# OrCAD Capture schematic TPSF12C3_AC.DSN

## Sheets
1 Test Bench: size C
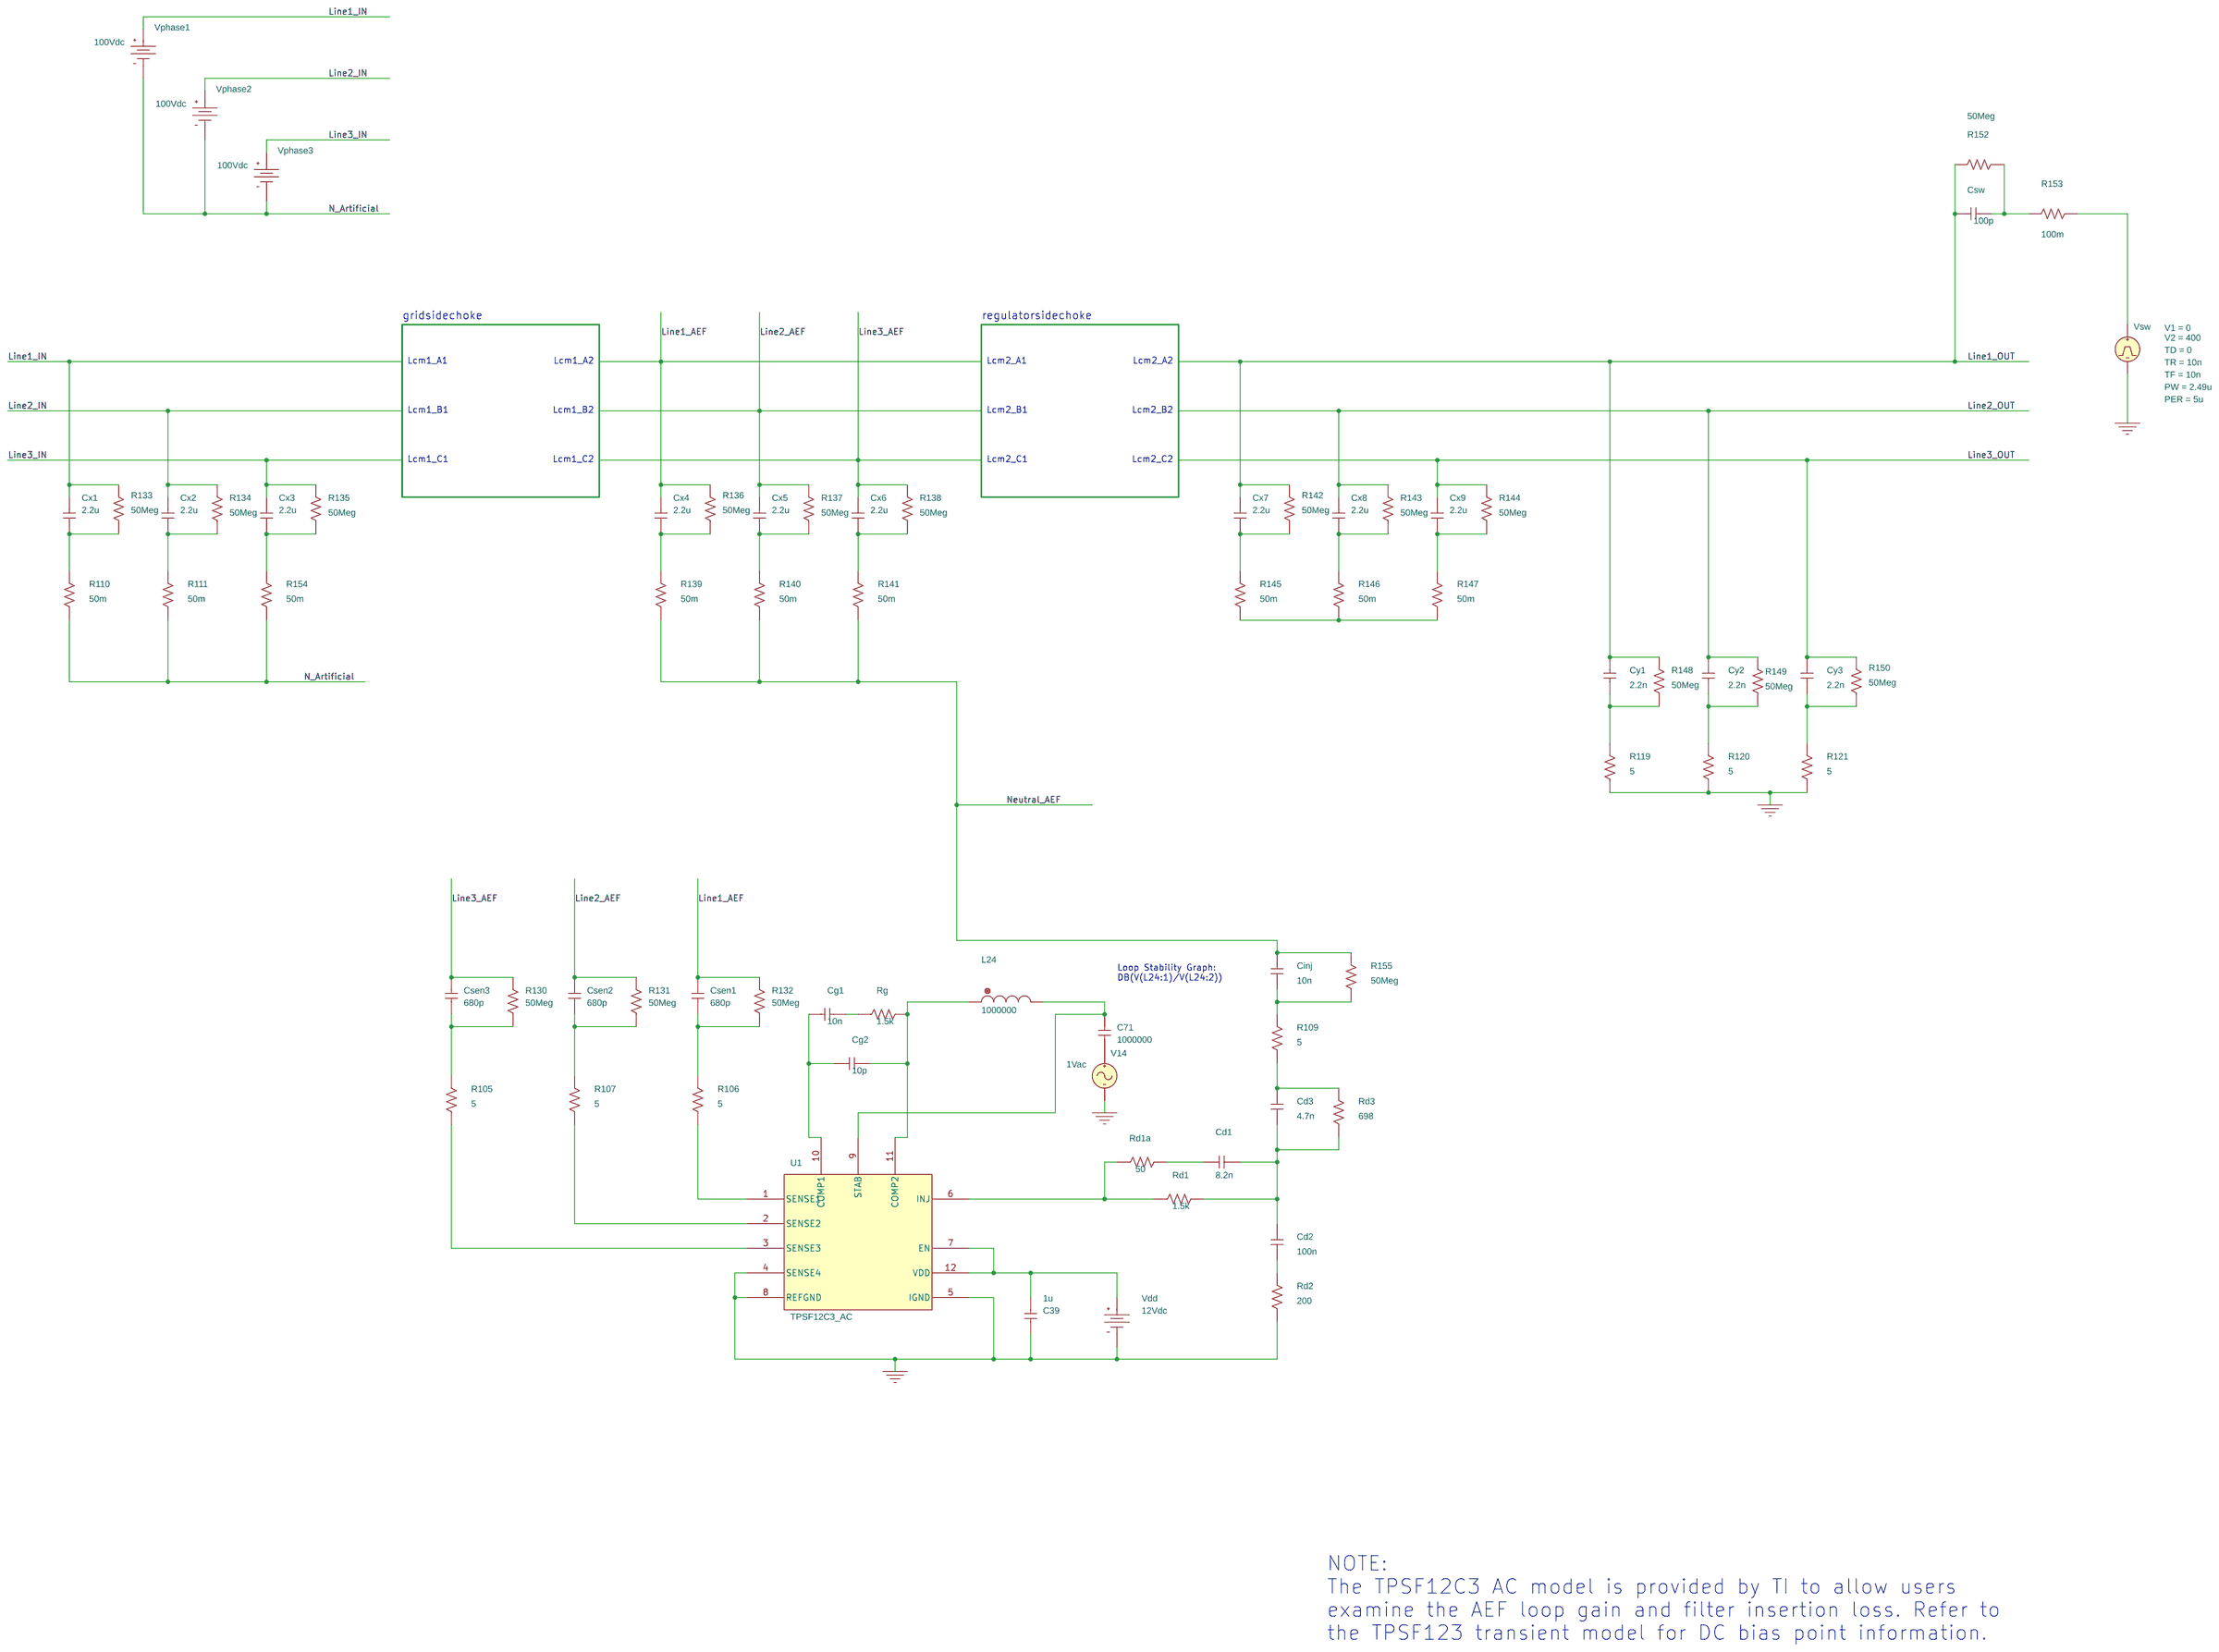
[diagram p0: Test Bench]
2 3 wire choke model: size C; block regulatorsidechoke
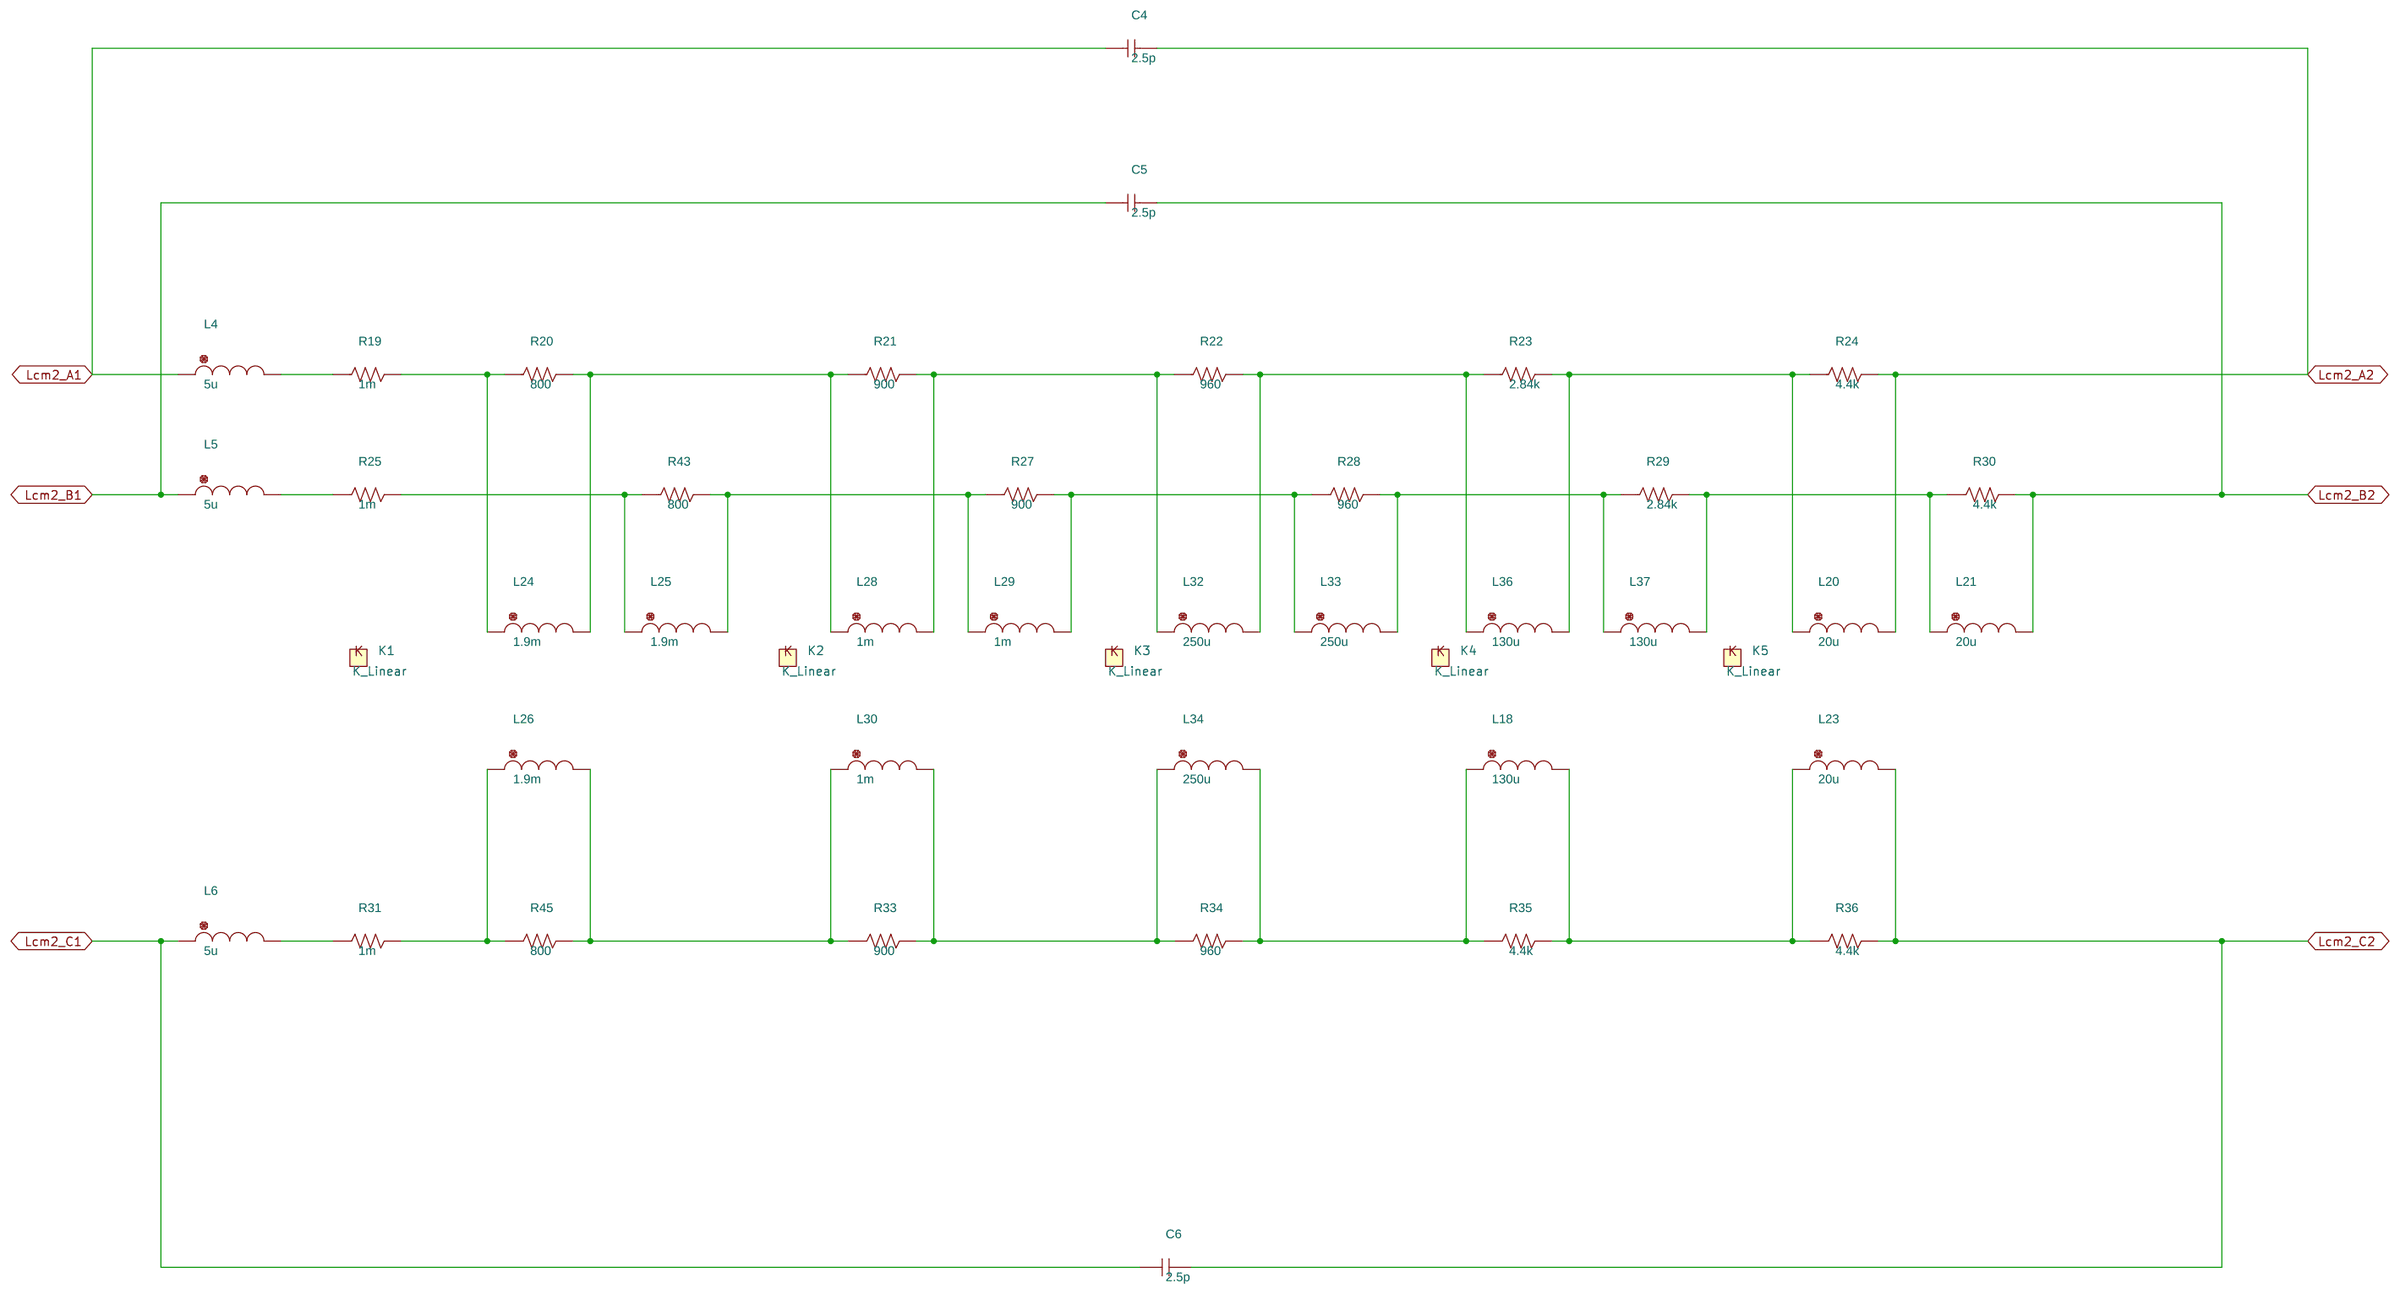
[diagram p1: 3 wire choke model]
3 3 wire choke model (2): size B; block gridsidechoke
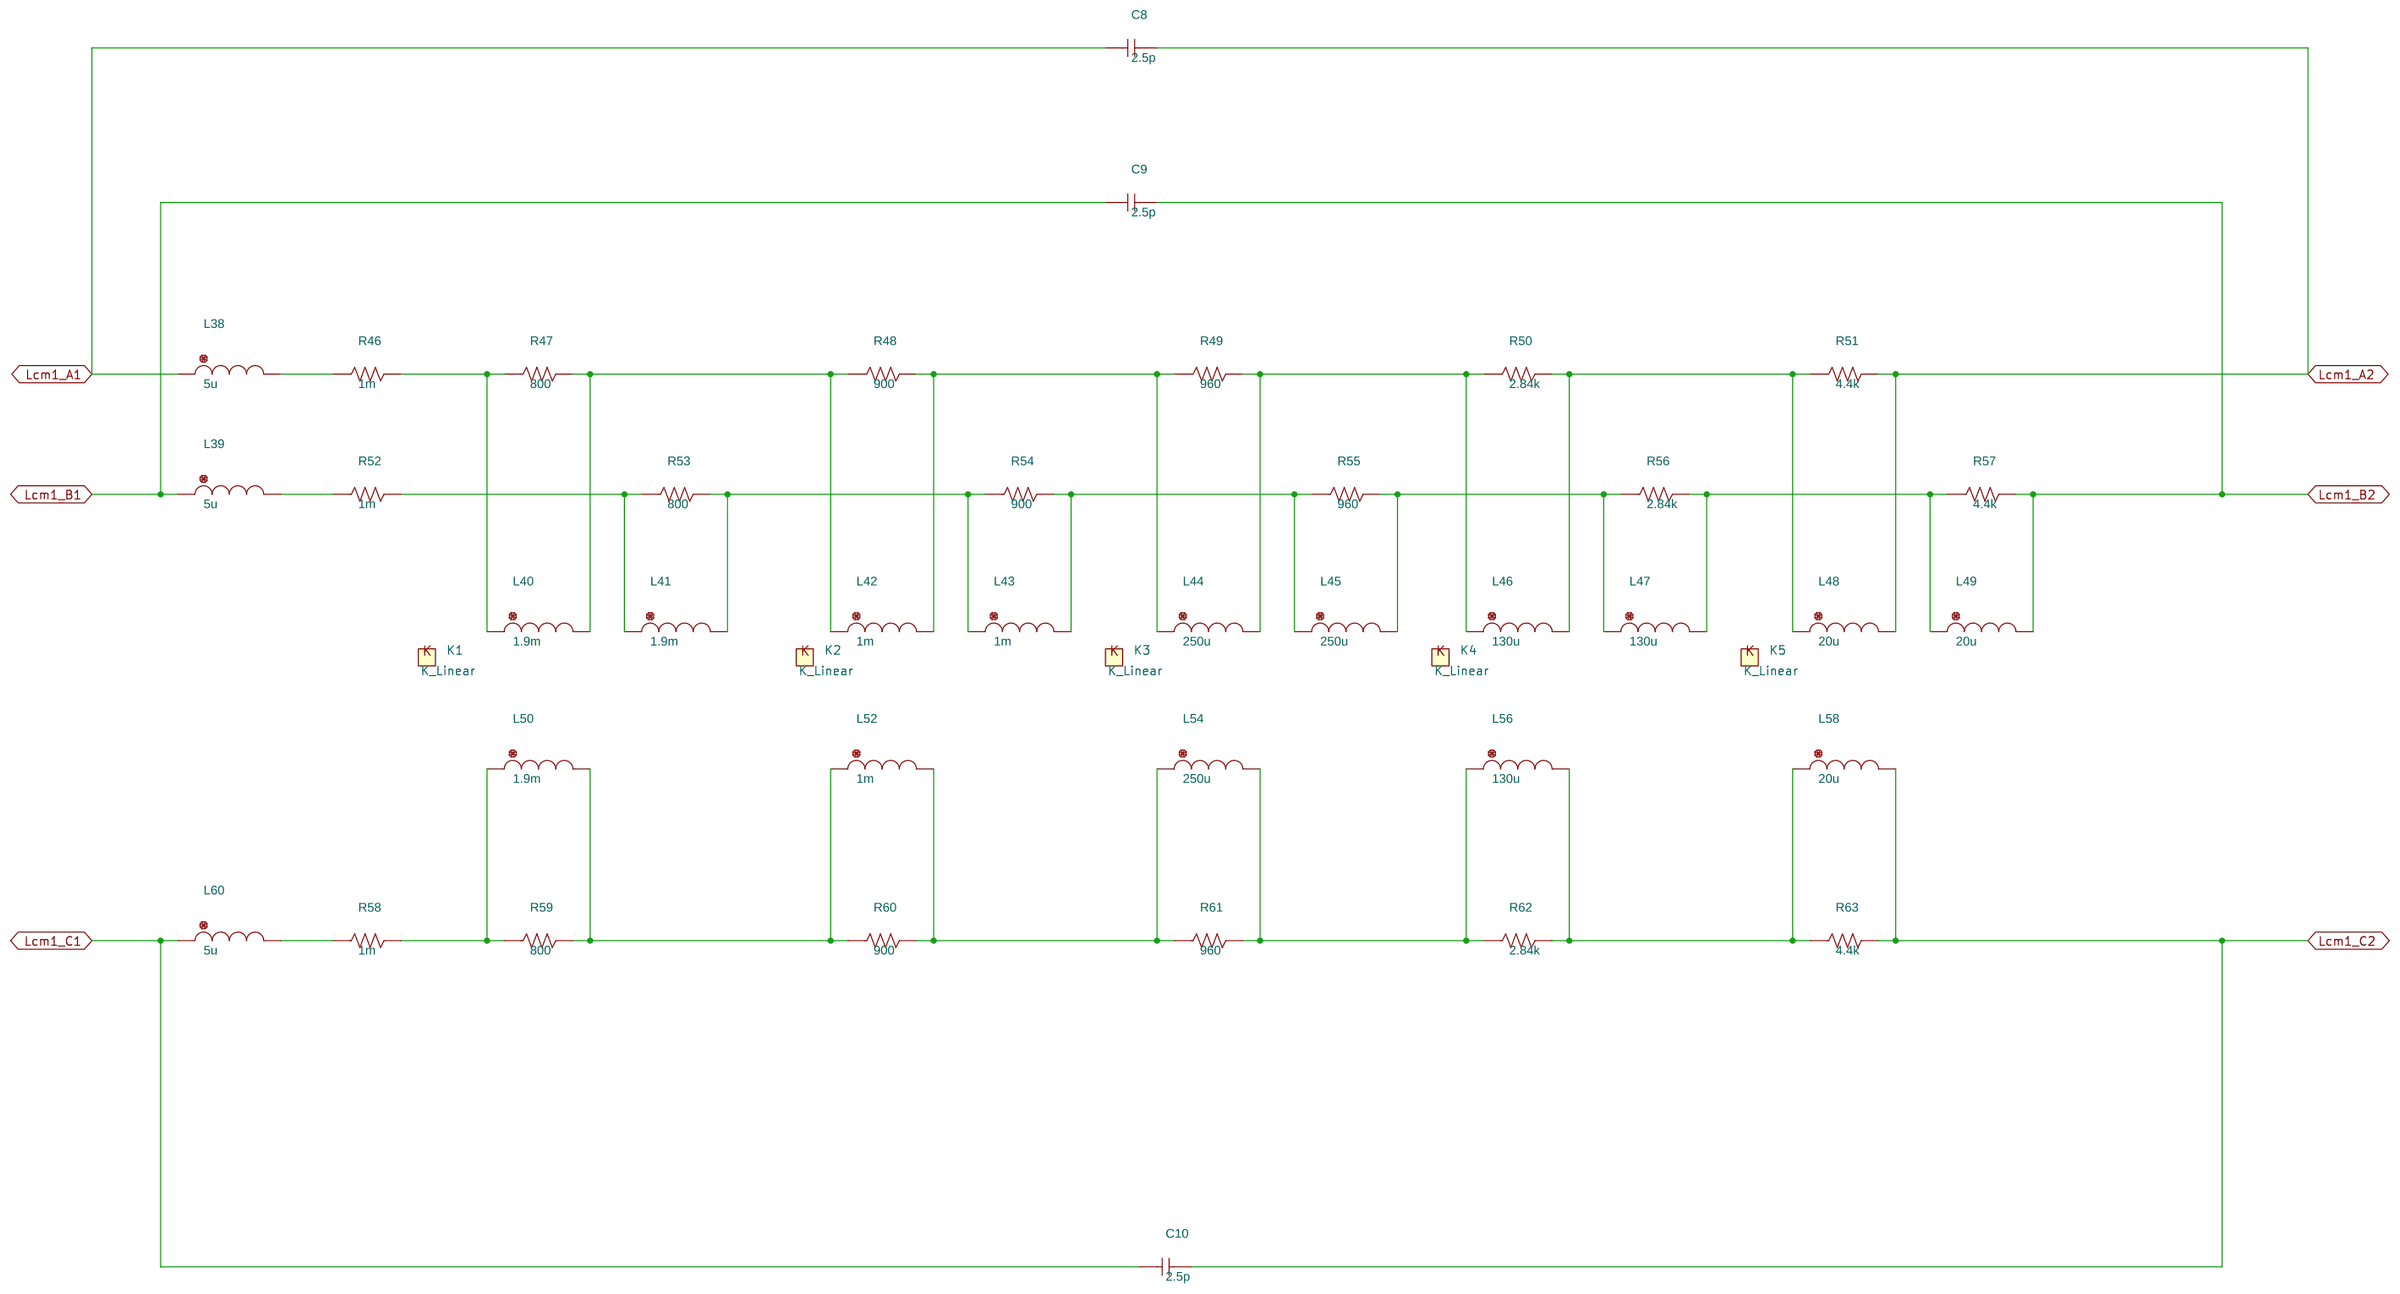
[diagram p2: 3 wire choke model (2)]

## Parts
sheet 3 wire choke model (2)
C8  2.5p  [cap196]
C9  2.5p  [cap196]
C10  2.5p  [cap196]
L38  5u  [DISC350x175LS200x100034]
L39  5u  [DISC350x175LS200x100034]
L40  1.9m  [DISC350x175LS200x100034]
L41  1.9m  [DISC350x175LS200x100034]
L42  1m  [DISC350x175LS200x100034]
L43  1m  [DISC350x175LS200x100034]
L44  250u  [DISC350x175LS200x100034]
L45  250u  [DISC350x175LS200x100034]
L46  130u  [DISC350x175LS200x100034]
L47  130u  [DISC350x175LS200x100034]
L48  20u  [DISC350x175LS200x100034]
L49  20u  [DISC350x175LS200x100034]
L50  1.9m  [DISC350x175LS200x100034]
L52  1m  [DISC350x175LS200x100034]
L54  250u  [DISC350x175LS200x100034]
L56  130u  [DISC350x175LS200x100034]
L58  20u  [DISC350x175LS200x100034]
L60  5u  [DISC350x175LS200x100034]
R46  1m  [AXRC05]
R47  800  [AXRC05]
R48  900  [AXRC05]
R49  960  [AXRC05]
R50  2.84k  [AXRC05]
R51  4.4k  [AXRC05]
R52  1m  [AXRC05]
R53  800  [AXRC05]
R54  900  [AXRC05]
R55  960  [AXRC05]
R56  2.84k  [AXRC05]
R57  4.4k  [AXRC05]
R58  1m  [AXRC05]
R59  800  [AXRC05]
R60  900  [AXRC05]
R61  960  [AXRC05]
R62  2.84k  [AXRC05]
R63  4.4k  [AXRC05]
sheet 3 wire choke model
C4  2.5p  [cap196]
C5  2.5p  [cap196]
C6  2.5p  [cap196]
K1  K_Linear
K2  K_Linear
K3  K_Linear
K4  K_Linear
K5  K_Linear
L4  5u  [DISC350x175LS200x100034]
L5  5u  [DISC350x175LS200x100034]
L6  5u  [DISC350x175LS200x100034]
L18  130u  [DISC350x175LS200x100034]
L20  20u  [DISC350x175LS200x100034]
L21  20u  [DISC350x175LS200x100034]
L23  20u  [DISC350x175LS200x100034]
L24  1.9m  [DISC350x175LS200x100034]
L24#2  1.9m  [DISC350x175LS200x100034]
L25  1.9m  [DISC350x175LS200x100034]
L26  1.9m  [DISC350x175LS200x100034]
L28  1m  [DISC350x175LS200x100034]
L29  1m  [DISC350x175LS200x100034]
L30  1m  [DISC350x175LS200x100034]
L32  250u  [DISC350x175LS200x100034]
L33  250u  [DISC350x175LS200x100034]
L34  250u  [DISC350x175LS200x100034]
L36  130u  [DISC350x175LS200x100034]
L37  130u  [DISC350x175LS200x100034]
R19  1m  [AXRC05]
R20  800  [AXRC05]
R21  900  [AXRC05]
R22  960  [AXRC05]
R23  2.84k  [AXRC05]
R24  4.4k  [AXRC05]
R25  1m  [AXRC05]
R27  900  [AXRC05]
R28  960  [AXRC05]
R29  2.84k  [AXRC05]
R30  4.4k  [AXRC05]
R31  1m  [AXRC05]
R33  900  [AXRC05]
R34  960  [AXRC05]
R35  4.4k  [AXRC05]
R36  4.4k  [AXRC05]
R43  800  [AXRC05]
R45  800  [AXRC05]
sheet Test Bench
C39  1u  [cap196]
C71  1000000  [cap196]
Cd1  8.2n  [cap196]
Cd2  100n  [cap196]
Cd3  4.7n  [cap196]
Cg1  10n  [cap196]
Cg2  10p  [cap196]
Cinj  10n  [cap196]
Csen1  680p  [cap196]
Csen2  680p  [cap196]
Csen3  680p  [cap196]
Csw  100p  [cap196]
Cx1  2.2u  [cap196]
Cx2  2.2u  [cap196]
Cx3  2.2u  [cap196]
Cx4  2.2u  [cap196]
Cx5  2.2u  [cap196]
Cx6  2.2u  [cap196]
Cx7  2.2u  [cap196]
Cx8  2.2u  [cap196]
Cx9  2.2u  [cap196]
Cy1  2.2n  [cap196]
Cy2  2.2n  [cap196]
Cy3  2.2n  [cap196]
R105  5  [AXRC05]
R106  5  [AXRC05]
R107  5  [AXRC05]
R109  5  [AXRC05]
R110  50m  [AXRC05]
R111  50m  [AXRC05]
R119  5  [AXRC05]
R120  5  [AXRC05]
R121  5  [AXRC05]
R130  50Meg  [AXRC05]
R131  50Meg  [AXRC05]
R132  50Meg  [AXRC05]
R133  50Meg  [AXRC05]
R134  50Meg  [AXRC05]
R135  50Meg  [AXRC05]
R136  50Meg  [AXRC05]
R137  50Meg  [AXRC05]
R138  50Meg  [AXRC05]
R139  50m  [AXRC05]
R140  50m  [AXRC05]
R141  50m  [AXRC05]
R142  50Meg  [AXRC05]
R143  50Meg  [AXRC05]
R144  50Meg  [AXRC05]
R145  50m  [AXRC05]
R146  50m  [AXRC05]
R147  50m  [AXRC05]
R148  50Meg  [AXRC05]
R149  50Meg  [AXRC05]
R150  50Meg  [AXRC05]
R152  50Meg  [AXRC05]
R153  100m  [AXRC05]
R154  50m  [AXRC05]
R155  50Meg  [AXRC05]
Rd1  1.5k  [AXRC05]
Rd1a  50  [AXRC05]
Rd2  200  [AXRC05]
Rd3  698  [AXRC05]
Rg  1.5k  [AXRC05]
U1  TPSF12C3_AC
V14  VAC
Vdd  VDC
Vphase1  VDC
Vphase2  VDC
Vphase3  VDC
Vsw  VPULSE

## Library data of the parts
C4-C6 C8-C10 C39 Cd1 Cd3 Cg1 Cg2 Cinj Csen1-Csen3 Csw Cx1-Cx9 Cy1-Cy3 = C
L4-L6 L18 L20 L21 L23 L24 L24#2 L25 L26 L28-L30 L32-L34 L36-L50 L52 L54 L56 L58 L60 = L
R19-R25 R27-R31 R33-R36 R43 R45-R63 R105-R107 R109-R111 R119-R121 R130-R150 R152-R155 Rd1 Rd1a Rd2 Rd3 Rg = R
K1 = K_Linear: L1: L24; L2: L25; L3: L26
K2 = K_Linear: L1: L28; L2: L29; L3: L30
K3 = K_Linear: L1: L32; L2: L33; L3: L34
K4 = K_Linear: L1: L36; L2: L37; L3: L18
K5 = K_Linear: L1: L20; L2: L21; L3: L23
C71 = C: IC: 0
Cd2 = C: IC: 6
U1 = TPSF12C3_AC
V14 = VAC: ACMAG: 1Vac
Vdd = VDC: DC: 12Vdc
Vphase1-Vphase3 = VDC: DC: 100Vdc
Vsw = VPULSE: PER: 5u; PW: 2.49u; TD: 0; TF: 10n; TR: 10n; V1: 0; V2: 400

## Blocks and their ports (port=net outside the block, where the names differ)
regulatorsidechoke = schematic 3 wire regulator side choke, on sheet Test Bench: Lcm2_A1=Line1_AEF, Lcm2_A2=Line1_OUT, Lcm2_B1=Line2_AEF, Lcm2_B2=Line2_OUT, Lcm2_C1=Line3_AEF, Lcm2_C2=Line3_OUT
gridsidechoke = schematic 3 wire grid side choke, on sheet Test Bench: Lcm1_A1=Line1_IN, Lcm1_A2=Line1_AEF, Lcm1_B1=Line2_IN, Lcm1_B2=Line2_AEF, Lcm1_C1=Line3_IN, Lcm1_C2=Line3_AEF

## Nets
0: C39.2 R119.1 R120.1 R121.1 Rd2.1 U1.4(SENSE4) U1.5(IGND) U1.8(REFGND) V14.2(-) Vdd.1(-) Vsw.2(-)
Line1_AEF: C4.1 C8.2 Csen1.2 Cx4.2 L4.1 L48.2 R51.2 R132.2 R136.2
Line1_IN: C8.1 Cx1.2 L38.1 R133.2 Vphase1.0(+)
Line1_OUT: C4.2 Csw.1 Cx7.2 Cy1.2 L20.2 R24.2 R142.2 R148.2 R152.2
Line2_AEF: C5.1 C9.2 Csen2.2 Cx5.2 L5.1 L49.2 R57.2 R131.2 R137.2
Line2_IN: C9.1 Cx2.2 L39.1 R134.2 Vphase2.0(+)
Line2_OUT: C5.2 Cx8.2 Cy2.2 L21.2 R30.2 R143.2 R149.2
Line3_AEF: C6.1 C10.2 Csen3.2 Cx6.2 L6.1 L58.2 R63.2 R130.2 R138.2
Line3_IN: C10.1 Cx3.2 L60.1 R135.2 Vphase3.0(+)
Line3_OUT: C6.2 Cx9.2 Cy3.2 L23.2 R36.2 R144.2 R150.2
N_Artificial: R110.1 R111.1 R154.1 Vphase1.1(-) Vphase2.1(-) Vphase3.1(-)
Neutral_AEF: Cinj.2 R139.1 R140.1 R141.1 R155.2
gridsidechoke/N35926: L38.2 R46.1
gridsidechoke/N35932: L40.1 R46.2 R47.1
gridsidechoke/N35946: L40.2 L42.1 R47.2 R48.1
gridsidechoke/N35968: L42.2 L44.1 R48.2 R49.1
gridsidechoke/N35990: L44.2 L46.1 R49.2 R50.1
gridsidechoke/N36012: L46.2 L48.1 R50.2 R51.1
gridsidechoke/N36214: L39.2 R52.1
gridsidechoke/N36220: L41.1 R52.2 R53.1
gridsidechoke/N36234: L41.2 L43.1 R53.2 R54.1
gridsidechoke/N36256: L43.2 L45.1 R54.2 R55.1
gridsidechoke/N36278: L45.2 L47.1 R55.2 R56.1
gridsidechoke/N36300: L47.2 L49.1 R56.2 R57.1
gridsidechoke/N36738: L50.1 R58.2 R59.1
gridsidechoke/N36744: L50.2 L52.1 R59.2 R60.1
gridsidechoke/N36752: L52.2 L54.1 R60.2 R61.1
gridsidechoke/N36760: L54.2 L56.1 R61.2 R62.1
gridsidechoke/N36768: L56.2 L58.1 R62.2 R63.1
gridsidechoke/N36954: L60.2 R58.1
N210526: Csw.2 R152.1 R153.2
N210582: R153.1 Vsw.1(+)
N211300: Cx1.1 R110.2 R133.1
N211310: Cx2.1 R111.2 R134.1
N211320: Cx3.1 R135.1 R154.2
N211330: Cx4.1 R136.1 R139.2
N211340: Cx5.1 R137.1 R140.2
N211350: Cx6.1 R138.1 R141.2
N211360: Cx7.1 R142.1 R145.2
N211370: Cx8.1 R143.1 R146.2
N211380: Cx9.1 R144.1 R147.2
N211626: R145.1 R146.1 R147.1
N211850: Cy1.1 R119.2 R148.1
N211854: Cy2.1 R120.2 R149.1
N211858: Cy3.1 R121.2 R150.1
N212286: Cinj.1 R109.2 R155.1
N212304: Csen3.1 R105.2 R130.1
N212308: Csen2.1 R107.2 R131.1
N212314: Csen1.1 R106.2 R132.1
N212400: Cg1.1 Cg2.1 U1.10(COMP1)
N212406: Cg1.2 Rg.1
N212412: Cg2.2 L24.1 Rg.2 U1.11(COMP2)
N212456: Cd3.2 R109.1 Rd3.2
N212620: R105.1 U1.3(SENSE3)
N212624: R107.1 U1.2(SENSE2)
N212628: R106.1 U1.1(SENSE1)
N212698: Cd1.1 Cd2.2 Cd3.1 Rd1.2 Rd3.1
N212764: Rd1.1 Rd1a.1 U1.6(INJ)
N212768: Cd1.2 Rd1a.2
N212844: C39.1 U1.7(EN) U1.12(VDD) Vdd.0(+)
N212882: Cd2.1 Rd2.2
N214754: C71.2 L24.2 U1.9(STAB)
N244736: C71.1 V14.1(+)
regulatorsidechoke/N45648: L4.2 R19.1
regulatorsidechoke/N45654: L24#2.1 R19.2 R20.1
regulatorsidechoke/N45668: L24#2.2 L28.1 R20.2 R21.1
regulatorsidechoke/N45690: L28.2 L32.1 R21.2 R22.1
regulatorsidechoke/N45712: L32.2 L36.1 R22.2 R23.1
regulatorsidechoke/N45734: L20.1 L36.2 R23.2 R24.1
regulatorsidechoke/N45940: L5.2 R25.1
regulatorsidechoke/N45946: L25.1 R25.2 R43.1
regulatorsidechoke/N45960: L25.2 L29.1 R27.1 R43.2
regulatorsidechoke/N45982: L29.2 L33.1 R27.2 R28.1
regulatorsidechoke/N46004: L33.2 L37.1 R28.2 R29.1
regulatorsidechoke/N46026: L21.1 L37.2 R29.2 R30.1
regulatorsidechoke/N46474: L26.1 R31.2 R45.1
regulatorsidechoke/N46480: L26.2 L30.1 R33.1 R45.2
regulatorsidechoke/N46488: L30.2 L34.1 R33.2 R34.1
regulatorsidechoke/N46496: L18.1 L34.2 R34.2 R35.1
regulatorsidechoke/N46504: L18.2 L23.1 R35.2 R36.1
regulatorsidechoke/N46694: L6.2 R31.1

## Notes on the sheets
sheet 1
- Loop Stability Graph:
  DB(V(L24:1)/V(L24:2))
- NOTE:
  The TPSF12C3 AC model is provided by TI to allow users
  examine the AEF loop gain and filter insertion loss. Refer to
  the TPSF123 transient model for DC bias point information.
